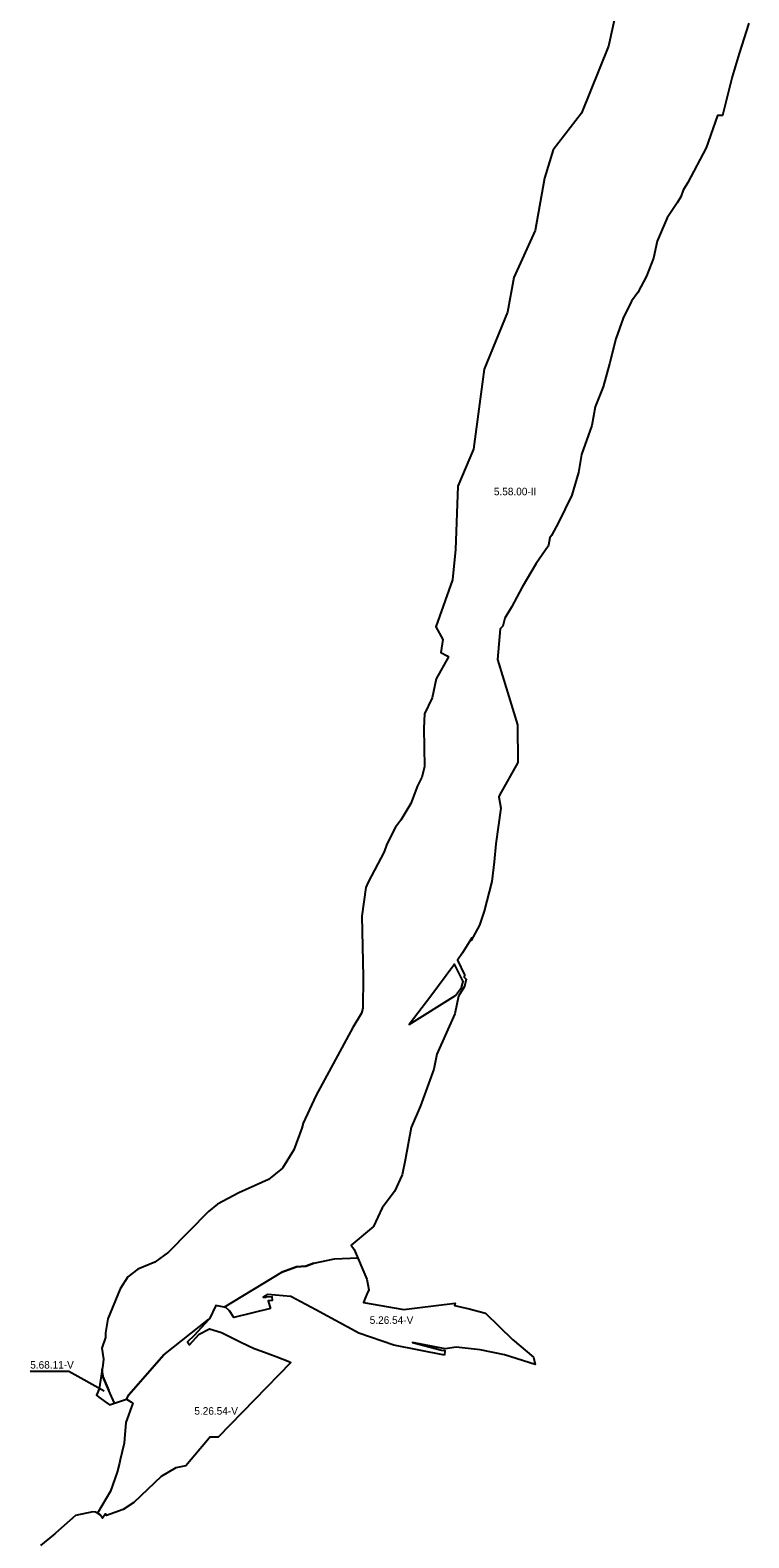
# Model space of a CAD drawing. Extents: x -547623 to -533936, y -1096714 to -1086523.
# Drawn here: x -546978 to -546022, y -1094374 to -1092367 of the extents above; entities that cross this region are included whole.
import ezdxf

# ---------------------------------------------------------------- set-up
doc = ezdxf.new("R2010")
doc.units = 0
doc.layers.add('Vrstva 27', color=7, linetype='Continuous')
doc.layers.add('Vrstva 28', color=7, linetype='Continuous')

msp = doc.modelspace()

# ---------------------------------------------------------------- linework, layer by layer
at = {"layer": 'Vrstva 27'}
msp.add_lwpolyline([(-546978.3, -1094152), (-546926.9, -1094152), (-546879.8, -1094178)], dxfattribs=at)
at = {"layer": 'Vrstva 28'}
for p, q in [((-546624, -1094013), (-546643.5, -1094020)), ((-546611.5, -1094012), (-546624, -1094013)), ((-546611.5, -1094012), (-546601, -1094008)), ((-546601, -1094008), (-546611.5, -1094012)), ((-546800.5, -1094130), (-546740.3, -1094082.8)), ((-546800.5, -1094130), (-546847, -1094183.5)), ((-546881.5, -1094159), (-546882.3, -1094148.7)), ((-546881.9, -1094154.4), (-546881.5, -1094159)), ((-546881.5, -1094159), (-546873.5, -1094177.4)), ((-546886.8, -1094186.6), (-546887, -1094186.5)), ((-546842.5, -1094193.9), (-546842.5, -1094193.8))]:
    msp.add_line(p, q, dxfattribs=at)
for points in [[(-546197.1, -1092336), (-546208.5, -1092388.3), (-546244.8, -1092477.6), (-546282.4, -1092526.1), (-546293.7, -1092563.8), (-546306.1, -1092633.5), (-546334.8, -1092696.1), (-546343.1, -1092742.2), (-546374.2, -1092818.2), (-546388.2, -1092924.6), (-546409.2, -1092974.1), (-546412.1, -1093058), (-546416.4, -1093098.4), (-546438.6, -1093161), (-546429.2, -1093178), (-546432, -1093195.2), (-546423.5, -1093199.9), (-546421.7, -1093200.9), (-546437.8, -1093230.5), (-546443.3, -1093255.6), (-546453.3, -1093276.7), (-546454.6, -1093296), (-546453.6, -1093347.4), (-546457.2, -1093361.1), (-546462.9, -1093372.6), (-546471.6, -1093396.4), (-546484.8, -1093418.3), (-546492.1, -1093427.8), (-546503.8, -1093450.4), (-546507, -1093460.6), (-546528.5, -1093500.9), (-546531.4, -1093508.2), (-546536.7, -1093546.4), (-546535.3, -1093626.8), (-546535.7, -1093668.6), (-546537.2, -1093675.5), (-546549.1, -1093694.6), (-546598, -1093785.4), (-546615.1, -1093821.7), (-546616.9, -1093828.4), (-546627.3, -1093857), (-546642.4, -1093881.4), (-546661.2, -1093896.9), (-546700.7, -1093914.4), (-546729, -1093929.5), (-546740.9, -1093939.2), (-546794.3, -1093993.2), (-546812.5, -1094006.5), (-546835.1, -1094016.2), (-546848.1, -1094026.2), (-546858.7, -1094042.2), (-546875, -1094082.1), (-546878.2, -1094100.7), (-546878.2, -1094107.1), (-546882.8, -1094121), (-546880.7, -1094135.8), (-546881.6, -1094144), (-546886.4, -1094175.3), (-546890.2, -1094183.9), (-546887, -1094186.5), (-546884, -1094188.6), (-546875.7, -1094194.5), (-546875.5, -1094194.6), (-546875, -1094195), (-546872.7, -1094196.6), (-546850.2, -1094188.9), (-546847.9, -1094190.3), (-546844.3, -1094192.6), (-546842.5, -1094193.8), (-546841.8, -1094194.3), (-546850.9, -1094220.1), (-546852.7, -1094241.7), (-546853.2, -1094247.5), (-546858.4, -1094269.9), (-546859.4, -1094274.2), (-546862.3, -1094286.4), (-546871.4, -1094311.5), (-546888.7, -1094341), (-546891.4, -1094339.6), (-546894.8, -1094339.2), (-546917.9, -1094344.1), (-546944.6, -1094367.4), (-546947.6, -1094370.1), (-546964.3, -1094383.9)], [(-546021.9, -1092357.6), (-546035, -1092398.1), (-546043.9, -1092429.1), (-546057.1, -1092480.6), (-546060.2, -1092480.6), (-546063.8, -1092480.4), (-546078.5, -1092523.4), (-546103.3, -1092569.9), (-546109.4, -1092579.9), (-546112.3, -1092588.9), (-546117.5, -1092597), (-546130.4, -1092616.6), (-546144, -1092647.8), (-546148.8, -1092670.4), (-546158.3, -1092694.3), (-546169.7, -1092716.3), (-546178.1, -1092727.6), (-546189.2, -1092750.4), (-546198.9, -1092778), (-546207.5, -1092811), (-546215.9, -1092841.7), (-546226.4, -1092868.3), (-546230.9, -1092893.2), (-546244.4, -1092931.9), (-546248.5, -1092955.8), (-546257.5, -1092985.9), (-546275.1, -1093022.4), (-546284.6, -1093039.5), (-546286.9, -1093042.8), (-546288.4, -1093052.5), (-546289, -1093053.6), (-546305, -1093076.8), (-546323.7, -1093108.3), (-546337.6, -1093134.8), (-546346.4, -1093149.6), (-546349.3, -1093160.2), (-546352.8, -1093163.6), (-546356.3, -1093204.7), (-546356.3, -1093204.8), (-546329.6, -1093291.7), (-546329.5, -1093341.7), (-546353.6, -1093385.3), (-546354.7, -1093387.4), (-546351.8, -1093402.5), (-546358.6, -1093449.9), (-546360.7, -1093474.1), (-546363.7, -1093500.2), (-546373.9, -1093539.6), (-546380.5, -1093558.3), (-546391.2, -1093578.6), (-546390.6, -1093574.9), (-546391.8, -1093577.2), (-546402.8, -1093595.2), (-546409.5, -1093604.7), (-546400.2, -1093624.3), (-546400.8, -1093627.2), (-546398.1, -1093630.2), (-546400.4, -1093639.9), (-546408.1, -1093652.6), (-546413.3, -1093676.4), (-546437, -1093730.1), (-546441.1, -1093749.7), (-546458.8, -1093798.5), (-546471.3, -1093827.5), (-546479.4, -1093871.1), (-546483.4, -1093890.6), (-546493.3, -1093912.7), (-546509.9, -1093934.4), (-546521.3, -1093959.4), (-546550.9, -1093984.2), (-546547, -1093989.7), (-546530.4, -1094029.2), (-546527.5, -1094043.5), (-546530.4, -1094049.4), (-546532.5, -1094054.7), (-546534.8, -1094060.6), (-546481, -1094069.6), (-546463.1, -1094067.4), (-546412.9, -1094061.4), (-546413.5, -1094064.5), (-546394.1, -1094068.8), (-546372.3, -1094074.8), (-546336.3, -1094109.8), (-546308.4, -1094133.1), (-546306.2, -1094142.9), (-546347.1, -1094130.1), (-546379.4, -1094123.5), (-546411.4, -1094119.8), (-546425.9, -1094122.1), (-546469.7, -1094113.7), (-546430.8, -1094124), (-546426.3, -1094124.5), (-546427.1, -1094130.6)], [(-546412.2, -1093651.8), (-546404.5, -1093641), (-546402.1, -1093633.3), (-546413.5, -1093610.3), (-546414.3, -1093611.5), (-546445, -1093652.5), (-546473.8, -1093690.6), (-546412.2, -1093651.8)], [(-546720.2, -1094066.7), (-546643.5, -1094020), (-546624, -1094013), (-546611.5, -1094012), (-546601, -1094008), (-546573.5, -1094002.5), (-546542.2, -1094001.1)], [(-546427.1, -1094130.6), (-546494.5, -1094117.4), (-546541, -1094101.3), (-546598.1, -1094070.3), (-546631.4, -1094052.3), (-546661.8, -1094049.9), (-546668.3, -1094053.1), (-546665.3, -1094053.1), (-546664.2, -1094053.1), (-546664.2, -1094053), (-546656.5, -1094052.5), (-546656.1, -1094057.6), (-546661.7, -1094058.1), (-546659.6, -1094064.4), (-546658.4, -1094068.4)], [(-546658.4, -1094068.4), (-546707.3, -1094080.5), (-546713, -1094071.7), (-546717.8, -1094067.2), (-546731.1, -1094064.6), (-546739.7, -1094082.2), (-546740.8, -1094083.3), (-546760, -1094104.5), (-546768.8, -1094112.8), (-546766.3, -1094116.6), (-546753.2, -1094102.5), (-546739.5, -1094095.4), (-546723.8, -1094100.2), (-546721.1, -1094101.6), (-546697.8, -1094113), (-546680.4, -1094121.6), (-546671.2, -1094124.9), (-546650.7, -1094132.2), (-546635, -1094138.4), (-546631.4, -1094140.4), (-546728.2, -1094239.8), (-546739, -1094239.7), (-546739.9, -1094240.8), (-546770.9, -1094277.7), (-546784.3, -1094280.4), (-546804.1, -1094292), (-546840.2, -1094326.8), (-546854.4, -1094335.8), (-546876.8, -1094344), (-546878.2, -1094341.8), (-546882.1, -1094347.5), (-546885.2, -1094342.9), (-546888.7, -1094341), (-546891.4, -1094339.6), (-546894.8, -1094339.2), (-546917.9, -1094344.1), (-546944.6, -1094367.4), (-546947.6, -1094370.1), (-546964.3, -1094383.9)], [(-546850.2, -1094188.9), (-546847, -1094183.5), (-546800.5, -1094130)], [(-546866.1, -1094194.3), (-546873.5, -1094177.4), (-546881.5, -1094159)]]:
    msp.add_lwpolyline(points, dxfattribs=at)

# ---------------------------------------------------------------- texts
at = {"layer": 'Vrstva 27'}
for s, p in [('5.58.00-II', (-546361.2, -1092986)), ('5.26.54-V', (-546526.4, -1094088.8)), ('5.68.11-V', (-546978.2, -1094148.4)), ('5.26.54-V', (-546759.8, -1094209.7))]:
    msp.add_text(s, height=10, dxfattribs=at).set_placement(p)

doc.saveas('drawing.dxf')
